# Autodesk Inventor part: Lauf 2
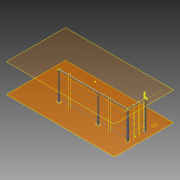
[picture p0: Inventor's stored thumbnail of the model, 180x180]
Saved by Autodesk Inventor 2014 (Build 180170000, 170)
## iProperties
Created: 2013-09
Part Number: Lauf 2
Material: Edelstahl
Document SubType Name: Modeling
Designer: Stefan Tammegger
Mass: 13427.2 g
Surface Area: 16641.2 cm^2
Volume: 1661.78 cm^3
Density: 8.08 g/cm^3
Appearance: Halbpoliert
Author: Stefan Tammegger
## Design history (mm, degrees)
workplane "Arbeitsebene1"
workplane "Arbeitsebene2"
sketch "Skizze2"
  geometry: L1 (1495.256, -384.789)-(1459.582, 977.565) reference; L2 (-952.744, -384.789)-(1495.256, -384.789) reference; L3 (1420.067, 385.507)-(1442.476, -470.273); L4 (-1051.75, -269.784)-(1558.665, -269.784); L5 (1494.11, 387.446)-(1544.093, 388.755) reference; L6 (1494.11, 387.446)-(1305.598, 382.51); 3 further points
  constraints: 6 end point, 4 point on line, 2 parallel, 1 collinear
  node "Referenz8"
  node "Referenz9"
  node "Referenz16"
sketch "3D-Skizze1"
feature "Sweeping1" sketch "3D-Skizze1" dims "d15" = 0
workpoint "Arbeitspunkt1"
workplane "Arbeitsebene3"
sketch "Skizze3"
  geometry: L1 (-7.227, 54.665)-(59.526, 54.665); L2 (59.526, 54.665)-(59.526, -6.619); L3 (59.526, -6.619)-(-7.227, -6.619); L4 (-7.227, -6.619)-(-7.227, 54.665); 1 further point
  constraints: 8 end point, 2 parallel, 1 horizontal, 1 perpendicular
feature "Umgrenzungsfläche1" sketch "Skizze3"
feature "Trennen1"
  node "Volumenkörper1"
workplane "Arbeitsebene4"
sketch "Skizze4"
  geometry: L1 (-6.096, 78.721)-(40.067, 78.721); L2 (40.067, 78.721)-(40.067, -8.633); L3 (40.067, -8.633)-(-6.096, -8.633); L4 (-6.096, -8.633)-(-6.096, 78.721); 1 further point
  constraints: 8 end point, 2 parallel, 1 horizontal, 1 perpendicular
feature "Umgrenzungsfläche2" sketch "Skizze4"
feature "Trennen2"
  node "Volumenkörper2"
workplane "Arbeitsebene5"
sketch "Skizze5"
  geometry: L1 (-10.077, 60.782)-(54.599, 60.782); L2 (54.599, 60.782)-(54.599, -10.925); L3 (54.599, -10.925)-(-10.077, -10.925); L4 (-10.077, -10.925)-(-10.077, 60.782); 1 further point
  constraints: 8 end point, 2 parallel, 1 horizontal, 1 perpendicular
feature "Umgrenzungsfläche3" sketch "Skizze5"
feature "Trennen3"
  node "Volumenkörper4"
workplane "Arbeitsebene6"
sketch "Skizze6"
  geometry: L1 (389.256, -399.789)-(389.256, -449.789) reference; L2 (359.256, -449.789)-(359.256, -399.789) reference; L3 (1462.889, -294.784)-(-1051.75, -294.784) reference; L4 (1411.563, -244.784)-(-1051.75, -244.784) reference; L5 (1395.075, 384.853)-(1411.563, -244.784) reference; L6 (1445.058, 386.162)-(1462.889, -294.784) reference; L7 (359.256, -294.784)-(389.256, -294.784); L8 (389.256, -294.784)-(389.256, -244.784); L9 (389.256, -244.784)-(359.256, -244.784); L10 (359.256, -244.784)-(359.256, -294.784); L11 (387.256, -246.784)-(387.256, -292.784); L12 (387.256, -292.784)-(361.256, -292.784); L13 (361.256, -292.784)-(361.256, -246.784); L14 (361.256, -246.784)-(387.256, -246.784); L15 (1411.563, -244.784)-(1461.563, -244.784); L16 (1461.563, -244.784)-(1461.563, -294.784); L17 (1461.563, -294.784)-(1411.563, -294.784); L18 (1411.563, -294.784)-(1411.563, -244.784); L19 (1459.563, -246.784)-(1413.563, -246.784); L20 (1413.563, -246.784)-(1413.563, -292.784); L21 (1413.563, -292.784)-(1459.563, -292.784); L22 (1459.563, -292.784)-(1459.563, -246.784); 1 further point
  constraints: 32 end point, 8 parallel, 4 perpendicular, 2 horizontal, 2 point on line, 6 other
  dimensions: "d16" = 30 distance of L8.end L9.end; "d17" = 30 distance between parallel lines of L8 L2; "d18" = 2 distance between parallel lines of L8 L11; "d19" = 50 distance of L16.end L17.end; "d20" = 50 distance of L15.end L16.end; "d21" = 2 distance between parallel lines of L15 L19
extrude "Extrusion1" new body sketch "Skizze6" stored distance "d22" = 10; taper "d23" = 0 deg
workplane "Arbeitsebene7"
sketch "Skizze7"
  geometry: L1 (-1051.75, -294.784)-(-1051.75, -244.784) reference; L2 (1411.563, -244.784)-(-1051.75, -244.784) reference; L3 (-1023.305, -244.784)-(-1023.305, -294.784) reference; L4 (1462.889, -294.784)-(-1051.75, -294.784) reference; L5 (389.256, -294.784)-(389.256, -244.784) reference; L6 (359.256, -244.784)-(359.256, -294.784) reference; L7 (1411.563, -244.784)-(1411.563, -294.784) reference; L8 (1461.563, -244.784)-(1411.563, -244.784) reference; L9 (1395.611, 364.394)-(1445.594, 365.703) reference; L10 (1445.058, 386.162)-(1395.075, 384.853) reference; L11 (1445.058, 386.162)-(1462.889, -294.784) reference; L12 (1395.075, 384.853)-(1411.563, -244.784) reference; L13 (-1091.744, -229.784)-(-1091.744, -309.784); L14 (-1091.744, -309.784)-(-981.744, -309.784); L15 (-981.744, -309.784)-(-981.744, -229.784); L16 (-981.744, -229.784)-(-1091.744, -229.784); L17 (-1051.744, -449.789)-(-1051.744, -399.789) reference; L18 (359.256, -399.789)-(359.256, -449.789) reference; L19 (429.256, -309.784)-(429.256, -229.784); L20 (429.256, -229.784)-(319.256, -229.784); L21 (319.256, -229.784)-(319.256, -309.784); L22 (319.256, -309.784)-(429.256, -309.784); C1 r 5.5 at (-996.744, -269.784); C2 r 5.5 at (-1076.744, -269.784); C3 r 5.5 at (414.256, -269.784); C4 r 5.5 at (334.256, -269.784); 1 further point
  constraints: 16 end point, 4 centre point, 4 parallel, 3 perpendicular
  dimensions: "d28" = 80 distance of L13.start L13.end; "d29" = 110 distance of L15.end L13.start; "d30" = 15 distance between parallel lines of L14 L4; "d33" = 40 distance between parallel lines of L17 L13; "d34" = 11 diameter of C1; "d35" = 11 diameter of C2; "d36" = 15 distance from line of L15 C1.centre; "d37" = 15 distance from line of L13 C2.centre; "d38" = 40 distance from line of L16 C1.centre; "d39" = 40 distance from line of L16 C2.centre; "d40" = 80 distance of L20.end L21.end; "d41" = 110 distance of L19.end L20.end; "d42" = 11 diameter of C3; "d43" = 11 diameter of C4; "d44" = 15 distance from line of L19 C3.centre; "d45" = 15 distance from line of L21 C4.centre; "d46" = 40 distance from line of L20 C3.centre; "d47" = 40 distance from line of L20 C4.centre; "d48" = 40 distance between parallel lines of L18 L21
extrude "Extrusion2" new body sketch "Skizze7" distance "d50" = 6; taper "d51" = 0 deg
fillet "Rundung1" dims "d52" = 4
workplane "Arbeitsebene8"
workplane "Arbeitsebene9"
feature "Trennen4"
feature "Trennen5"
workplane "Arbeitsebene10"
sketch "Skizze8"
  geometry: L1 (1395.075, 384.853)-(1411.563, -244.784) reference; L2 (1445.058, 386.162)-(1395.075, 384.853) reference; L3 (1445.058, 386.162)-(1462.889, -294.784) reference; L4 (1395.611, 364.394)-(1445.594, 365.703) reference; L5 (1535.143, 730.52)-(1485.16, 729.211) reference; L6 (1379.033, 424.446)-(1459.006, 426.54); L7 (1459.006, 426.54)-(1461.885, 316.578); L8 (1461.885, 316.578)-(1381.913, 314.484); L9 (1381.913, 314.484)-(1379.033, 424.446); C1 r 5.5 at (1419.412, 410.499); C2 r 5.5 at (1421.506, 330.526); 1 further point
  constraints: 8 end point, 3 parallel, 2 centre point, 1 perpendicular
  dimensions: "d57" = 80 distance of L6.start L6.end; "d58" = 110 distance of L8.end L6.start; "d59" = 15 distance between parallel lines of L7 L3; "d60" = 40 distance between parallel lines of L6 L2; "d61" = 11 diameter of C1; "d62" = 11 diameter of C2; "d63" = 15 distance from line of L6 C1.centre; "d64" = 40 distance from line of L9 C1.centre; "d65" = 40 distance from line of L9 C2.centre; "d66" = 15 distance from line of L8 C2.centre
extrude "Extrusion3" new body sketch "Skizze8" distance "d67" = 6; taper "d68" = 0 deg
workplane "Arbeitsebene11"
feature "Trennen6"
workplane "Arbeitsebene12"
sketch "Skizze9"
  geometry: L1 (1395.075, 384.853)-(1411.563, -244.784) reference; L2 (1411.563, -244.784)-(-1051.75, -244.784) reference; L3 (1445.058, 386.162)-(1462.889, -294.784) reference; L4 (1462.889, -294.784)-(-1051.75, -294.784) reference; L5 (1461.563, -244.784)-(1411.563, -244.784) reference; L6 (1411.563, -244.784)-(1411.563, -294.784) reference; L7 (1413.563, -246.784)-(1459.563, -246.784) reference; L8 (1413.563, -292.784)-(1413.563, -246.784) reference; L9 (1381.563, -214.784)-(1461.563, -214.784); L10 (1461.563, -214.784)-(1461.563, -294.784); L11 (1461.563, -294.784)-(1381.563, -294.784); L12 (1381.563, -294.784)-(1381.563, -214.784); C1 r 5.5 at (1436.563, -229.784); C2 r 5.5 at (1396.563, -269.784); 1 further point
  constraints: 8 end point, 2 centre point, 2 parallel, 1 horizontal, 1 perpendicular
  dimensions: "d70" = 80 distance of L9.start L9.end; "d71" = 80 distance of L11.end L9.start; "d72" = 30 distance between parallel lines of L6 L12; "d73" = 30 distance between parallel lines of L5 L9; "d74" = 11 diameter of C1; "d75" = 11 diameter of C2; "d76" = 15 distance from line of L9 C1.centre; "d77" = 15 distance from line of L12 C2.centre; "d78" = 25 distance from line of L4 C2.centre; "d79" = 25 distance from line of L10 C1.centre
extrude "Extrusion4" new body sketch "Skizze9" distance "d80" = 6; taper "d81" = 0 deg
workplane "Arbeitsebene13"
feature "Trennen7"
fillet "Rundung2" dims "d83" = 4
workplane "Arbeitsebene14"
sketch "Skizze10"
  geometry: L1 (-28.461, -0.012)-(-28.461, 49.989) reference; L2 (-28.461, -0.012)-(-28.445, 0) reference; L3 (-28.445, 50)-(-28.445, 0) reference; L4 (-28.461, 49.989)-(-28.445, 50) reference; L5 (-1020.001, -90.005)-(-1020.016, -90.016) reference; L6 (-1020.016, -90.016)-(-1020.016, 1272.337) reference; L7 (-1019.994, -90)-(-1019.994, -590) reference; L8 (-1020.001, -590.005)-(-1019.994, -590) reference; L9 (-1020.001, -90.005)-(-1020.001, -590.005) reference; L10 (0, 50)-(-1014, 49.995) reference; L11 (0, 0)-(-1014, -0.005) reference; C1 r 6 at (-248.461, 24.999); C2 r 6 at (-468.461, 24.998); C3 r 6 at (-688.461, 24.997); C4 r 6 at (-908.461, 24.996); 1 further point
  constraints: 4 centre point
  dimensions: "d85" = 12 diameter of C1; "d86" = 12 diameter of C2; "d87" = 12 diameter of C3; "d88" = 12 diameter of C4; "d89" = 220 distance from line of C1.centre L1; "d90" = 220 distance of C2.centre C1.centre; "d91" = 220 distance of C3.centre C2.centre; "d92" = 220 distance of C4.centre C3.centre; "d93" = 25 distance from line of L10 C1.centre; "d94" = 25 distance from line of L10 C2.centre; "d95" = 25 distance from line of L10 C3.centre; "d96" = 25 distance from line of L10 C4.centre
extrude "Extrusion5" new body sketch "Skizze10" stored distance "d97" = 6; taper "d98" = 0 deg
workplane "Arbeitsebene15"
sketch "Skizze11"
  geometry: L1 (0, 0)-(0, 50) reference; L2 (0, 50)-(0, 0) reference; C1 r 6 at (-220.007, 25.005) reference; C2 r 6 at (-440.007, 25.004) reference; C3 r 6 at (-660.007, 25.003) reference; C4 r 6 at (-880.007, 25.002) reference; C5 r 6 at (-220.007, 25.005); C6 r 6 at (-440.007, 25.004); C7 r 6 at (-660.007, 25.003); C8 r 6 at (-880.007, 25.002); 1 further point
  constraints: 4 centre point, 4 coincident, 4 concentric
extrude "Extrusion6" new body sketch "Skizze11" stored distance "d100" = 6; taper "d101" = 0 deg
feature "Trennen8"
sketch "Skizze13"
  geometry: L1 (1494.11, 387.446)-(1544.093, 388.755) reference; L2 (1494.895, 357.456)-(1494.11, 387.446) reference; L3 (1395.075, 384.853)-(1411.563, -244.784) reference; L4 (1445.058, 386.162)-(1395.075, 384.853) reference; L5 (1445.058, 386.162)-(1462.889, -294.784) reference; L6 (1395.075, 384.853)-(1395.861, 354.863); L7 (1395.861, 354.863)-(1445.843, 356.172); L8 (1445.843, 356.172)-(1445.058, 386.162); L9 (1445.058, 386.162)-(1395.075, 384.853); L10 (1397.127, 382.906)-(1397.808, 356.915); L11 (1397.808, 356.915)-(1443.792, 358.119); L12 (1443.792, 358.119)-(1443.111, 384.11); L13 (1443.111, 384.11)-(1397.127, 382.906); 1 further point
  constraints: 16 end point, 4 perpendicular, 3 parallel, 1 point on line, 1 other
  dimensions: "d119" = 30 distance of L6.start L6.end; "d120" = 50 distance of L6.end L7.end; "d121" = 30 distance of L7.end L8.end; "d122" = 0 distance between parallel lines of L4 L9; "d123" = 0 distance between parallel lines of L3 L6; "d124" = 2 distance between parallel lines of L4 L13; "d125" = 2 distance between parallel lines of L7 L11; "d126" = 2 distance between parallel lines of L6 L10
extrude "Extrusion8" new body sketch "Skizze13" distance "d127" = 1200; taper "d128" = 0 deg
workpoint "Arbeitspunkt2"
sketch "Skizze14"
  geometry: L1 (0, 0)-(0, 30) reference; L2 (0, 0)-(1200, 0) reference; L3 (1200, 30)-(1200, 0) reference; L4 (0, 30)-(1200, 30) reference; L5 (985.555, 9.534)-(985.555, -599.852) reference; 2 further points
  constraints: 2 point on line
workplane "Arbeitsebene17"
feature "Trennen9"
feature "Trennen10"
workplane "Arbeitsebene18"
workplane "Arbeitsebene19"
sketch "Skizze16"
  geometry: L1 (-0.654, 771.548)-(-1022.61, 771.548) reference; L2 (-0.654, 551.548)-(-1022.61, 551.548) reference; L3 (-0.654, 331.548)-(-1022.61, 331.548) reference; L4 (-0.654, 111.548)-(-1022.61, 111.548) reference; L5 (0, 0)-(0, 985.555) reference; L6 (0, 985.555)-(50, 985.555) reference; C1 r 6 at (25, 765.548); C2 r 6 at (25, 545.548); C3 r 6 at (25, 325.548); C4 r 6 at (25, 105.548); 1 further point
  constraints: 4 centre point
  dimensions: "d147" = 12 diameter of C1; "d148" = 12 diameter of C2; "d149" = 12 diameter of C3; "d150" = 12 diameter of C4; "d151" = 6 distance from line of C1.centre L1; "d152" = 25 distance from line of C1.centre L5; "d153" = 6 distance from line of L2 C2.centre; "d154" = 25 distance from line of C2.centre L5; "d155" = 6 distance from line of L3 C3.centre; "d156" = 25 distance from line of L5 C3.centre; "d157" = 25 distance from line of L5 C4.centre; "d158" = 6 distance from line of C4.centre L4
extrude "Extrusion10" new body sketch "Skizze16" stored distance "d159" = 1200; taper "d160" = 0 deg
node "Fläche1"
node "Fläche2"
node "Fläche3"
node "Referenz10"
node "Referenz11"
node "Volumenkörper8"
node "Referenz12"
node "Referenz13"
node "Volumenkörper9"
node "Referenz14"
node "Volumenkörper10"
node "Volumenkörper11"
node "Projizierte Kontur1"
node "Referenz15"
node "Volumenkörper12"
node "Projizierte Kontur2"
node "Volumenkörper13"
node "Referenz17"
node "Referenz18"
node "Volumenkörper15"
node "Volumenkörper17"
node "Volumenkörper3"
node "Volumenkörper5"
node "Volumenkörper6"
node "Volumenkörper7"
other parameters: "d10" = 0, "d12" = 2, "d53" = 0, "d54" = 0, "d69" = 0, "d82" = 0, "d84" = -388.75, "d99" = -414.25, "d129" = 202.75, "d145" = 212.75
